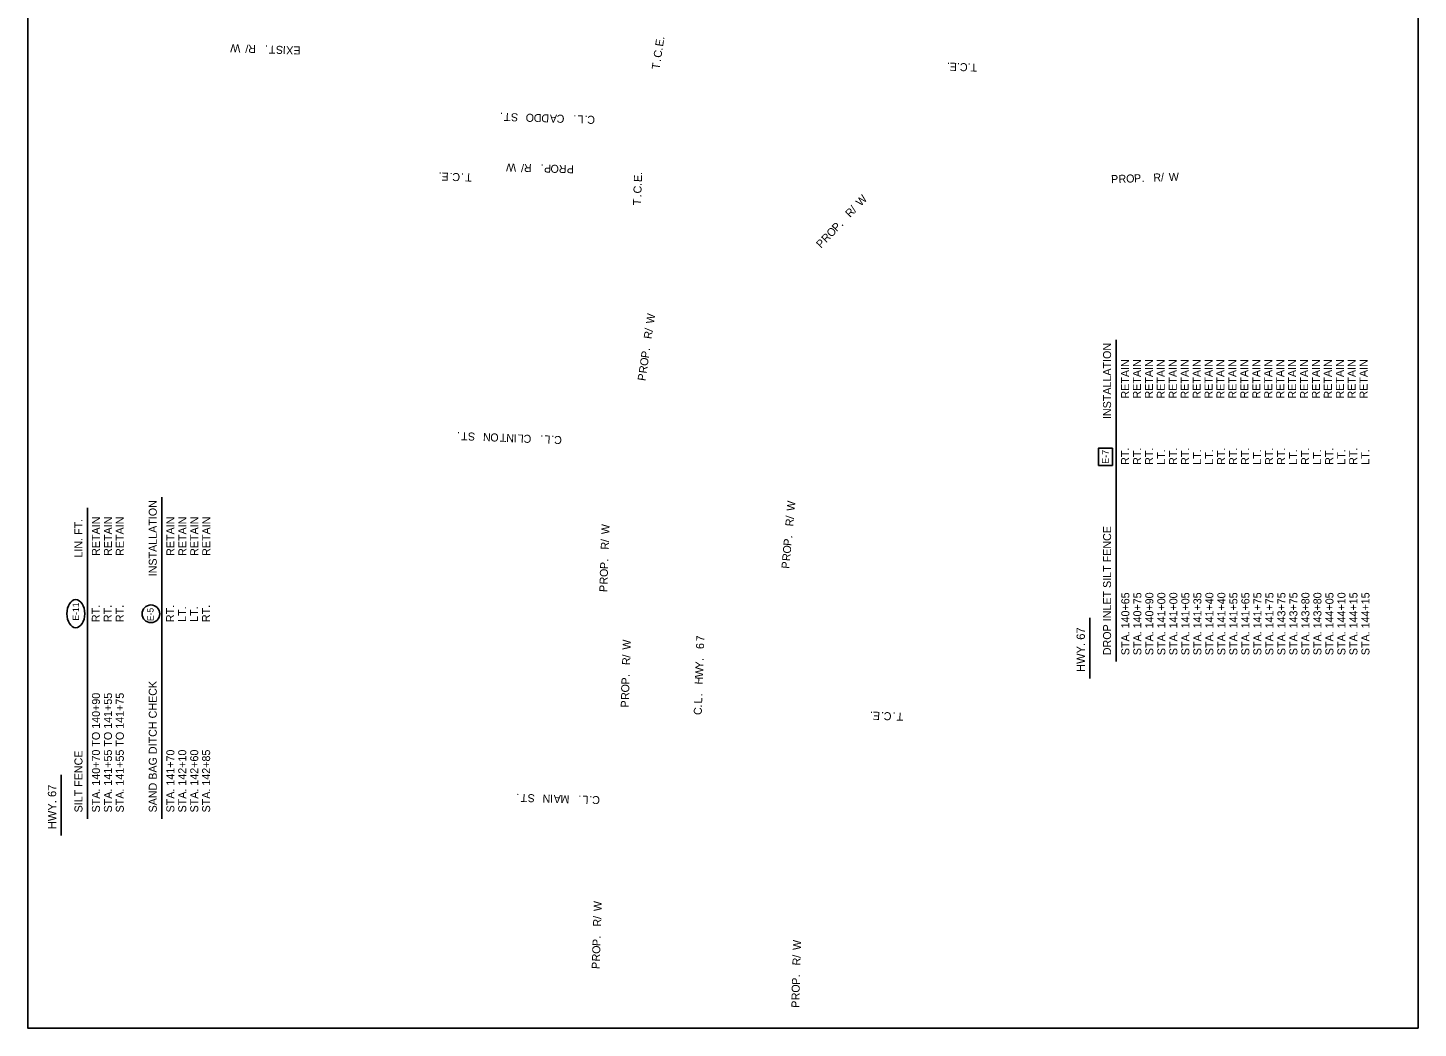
# Model space of a CAD drawing. Extents: x 991974 to 993016, y 1842702 to 1844298.
# Drawn here: x 991974 to 993016, y 1842702 to 1843452 of the extents above; entities that cross this region are included whole.
import ezdxf

# ---------------------------------------------------------------- set-up
doc = ezdxf.new("R2010")
doc.units = 0
for name, color, linetype in [('1', 7, 'Continuous'), ('44', 7, 'Continuous'), ('Default', 7, 'Continuous'), ('R_Draft', 7, 'Continuous')]:
    doc.layers.add(name, color=color, linetype=linetype)

msp = doc.modelspace()

# ---------------------------------------------------------------- linework, layer by layer
at = {"layer": '1'}
msp.add_lwpolyline([(992776.6, 1843124.1), (992776.6, 1843136.9), (992787.1, 1843136.9), (992787.1, 1843124.1)], close=True, dxfattribs=at)
msp.add_circle((992066.3, 1843012.9), 6.61, dxfattribs=at)
msp.add_ellipse((992010, 1843013), major_axis=(0, 10.5), ratio=0.638788, dxfattribs=at)
at = {"layer": '44'}
for p, q in [((992789.9, 1842977.1), (992789.9, 1843218.1)), ((992074.5, 1842859.4), (992074.5, 1843100.4)), ((992018.7, 1842859.4), (992018.7, 1843092.2)), ((992770.3, 1842964.4), (992770.3, 1843010)), ((991999.1, 1842846.7), (991999.1, 1842892.2))]:
    msp.add_line(p, q, dxfattribs=at)
at = {"layer": 'Default'}
msp.add_lwpolyline([(993016.3, 1842702.5), (991974, 1842702.5), (991974, 1843999.5), (992023.6, 1843999.5), (992023.6, 1844170.3), (992171.1, 1844170.3), (992171.1, 1844297.8), (993016.3, 1844297.8)], close=True, dxfattribs=at)
msp.add_lwpolyline([(993016.3, 1842702.5), (991974, 1842702.5), (991974, 1843999.5), (992023.6, 1843999.5), (992023.6, 1844170.3), (992171.1, 1844170.3), (992171.1, 1844297.8), (993016.3, 1844297.8)], close=True, dxfattribs=at)
msp.add_lwpolyline([(993016.3, 1842702.5), (991974, 1842702.5), (991974, 1843999.5), (992023.6, 1843999.5), (992023.6, 1844170.3), (992171.1, 1844170.3), (992171.1, 1844297.8), (993016.3, 1844297.8)], close=True, dxfattribs=at)

# ---------------------------------------------------------------- texts
at = {"layer": '1'}
for s, height, rotation, p in [('E-7 ', 5, 89.6132, (992784.3, 1843125.3)), ('E-11', 4.8, 90, (992012.4, 1843007.8)), ('E-5 ', 4.8, 90, (992068.3, 1843007.4))]:
    msp.add_text(s, height=height, rotation=rotation, dxfattribs=at).set_placement(p)
at = {"layer": '44'}
for s, height, p in [('INSTALLATION', 6, (992786.1, 1843158.8)), ('RT.', 6, (992799.6, 1843124.5)), ('RT.', 6, (992808.6, 1843124.5)), ('RT.', 6, (992817.6, 1843124.5)), ('LT.', 6, (992898.6, 1843124.6)), ('LT.', 6, (992925.6, 1843124.6)), ('LT.', 6, (992943.6, 1843124.6)), ('RT.', 6, (992952.6, 1843124.5)), ('LT.', 6, (992961.6, 1843124.6)), ('RT.', 6, (992970.6, 1843124.5)), ('LT.', 6, (992979.6, 1843124.6)), ('INSTALLATION', 6, (992070.7, 1843041)), ('LIN. FT.', 6, (992015, 1843055)), ('RETAIN', 6, (992028.1, 1843056.3)), ('RETAIN', 6, (992037.1, 1843056.3)), ('RETAIN', 6, (992046, 1843056.3)), ('DROP INLET SILT FENCE', 6, (992786.1, 1842981.9)), ('RT.', 6, (992028, 1843006.7)), ('RT.', 6, (992036.9, 1843006.7)), ('RT.', 6, (992045.9, 1843006.7)), ('HWY. 67', 6.25, (992766.5, 1842969.3)), ('SAND BAG DITCH CHECK', 6, (992070.7, 1842864.1)), ('STA. 140+70 TO 140+90', 6, (992028.1, 1842864.1)), ('STA. 141+55 TO 141+55', 6, (992037.1, 1842864.1)), ('STA. 141+55 TO 141+75', 6, (992046, 1842864.1)), ('SILT FENCE      ', 6, (992015, 1842864.1)), ('HWY. 67', 6.25, (991995.3, 1842851.5))]:
    msp.add_text(s, height=height, rotation=90, dxfattribs=at).set_placement(p)
at = {"layer": 'R_Draft'}
for s, rotation, p in [('W', 178.0557, (992133.5, 1843439.4)), ('/', 178.0557, (992139.4, 1843439.2)), ('R', 178.0557, (992145.1, 1843439)), ('.', 178.0557, (992154, 1843438.7)), ('T', 178.0557, (992159.8, 1843438.5)), ('S', 178.0557, (992165.5, 1843438.3)), ('I', 178.0557, (992167.5, 1843438.2)), ('X', 178.0557, (992173.2, 1843438)), ('E', 178.0557, (992178.6, 1843437.9)), ('E', 81.3131, (992450.2, 1843437.6)), ('.', 81.3131, (992451, 1843442.9)), ('C', 81.3131, (992448.9, 1843429.1)), ('.', 81.3131, (992448.5, 1843426.2)), ('.', 81.3131, (992449.8, 1843434.7)), ('T', 81.3131, (992447.6, 1843420.4)), ('T.C.E.', 178.0361, (992685.8, 1843425.1)), ('.', 178.1194, (992330.2, 1843388.2)), ('T', 178.1194, (992336, 1843388)), ('S', 178.1194, (992341.7, 1843387.8)), ('O', 178.1194, (992353.6, 1843387.4)), ('D', 178.1194, (992359.2, 1843387.2)), ('D', 178.1194, (992364.9, 1843387)), ('A', 178.1194, (992370.8, 1843386.8)), ('C', 178.1194, (992376.4, 1843386.7)), ('.', 178.1194, (992385.3, 1843386.4)), ('L', 178.1194, (992390.7, 1843386.2)), ('.', 178.1194, (992393.7, 1843386.1)), ('C', 178.1194, (992399.3, 1843385.9)), ('.', 178.0318, (992284.2, 1843343.5)), ('E', 178.0318, (992289.6, 1843343.3)), ('.', 178.0318, (992292.5, 1843343.2)), ('C', 178.0318, (992298.2, 1843343)), ('.', 178.0318, (992301.1, 1843342.9)), ('W', 178.425, (992340.2, 1843350.1)), ('/', 178.425, (992346.1, 1843349.9)), ('R', 178.425, (992351.8, 1843349.8)), ('.', 178.425, (992360.7, 1843349.5)), ('P', 178.425, (992366.4, 1843349.4)), ('O', 178.425, (992372.2, 1843349.2)), ('R', 178.425, (992377.9, 1843349.1)), ('P', 178.425, (992383.5, 1843348.9)), ('.', 88.0361, (992434.5, 1843341.7)), ('/', 2.1217, (992823.6, 1843336.9)), ('W', 2.1217, (992829.5, 1843337.1)), ('T', 178.0318, (992307, 1843342.7)), ('C', 88.0361, (992434, 1843327.7)), ('E', 88.0361, (992434.3, 1843336.3)), ('.', 88.0361, (992434.2, 1843333.4)), ('P', 2.1217, (992786.2, 1843335.5)), ('R', 2.1217, (992791.8, 1843335.7)), ('O', 2.1217, (992797.5, 1843335.9)), ('P', 2.1217, (992803.4, 1843336.1)), ('.', 2.1217, (992809, 1843336.4)), ('R', 2.1217, (992817.9, 1843336.7)), ('T', 88.0361, (992433.7, 1843318.9)), ('.', 88.0361, (992433.9, 1843324.8)), ('W', 46.5037, (992598.5, 1843317.8)), ('R', 46.5037, (992590.5, 1843309.4)), ('/', 46.5037, (992594.4, 1843313.5)), ('O', 46.5037, (992576.5, 1843294.6)), ('P', 46.5037, (992580.5, 1843298.8)), ('.', 46.5037, (992584.4, 1843302.9)), ('P', 46.5037, (992568.7, 1843286.4)), ('R', 46.5037, (992572.6, 1843290.5)), ('W', 81.6959, (992443.3, 1843229.9)), ('R', 81.6959, (992441.6, 1843218.5)), ('/', 81.6959, (992442.5, 1843224.1)), ('P', 81.6959, (992439.5, 1843204.1)), ('.', 81.6959, (992440.3, 1843209.7)), ('R', 81.6959, (992437.9, 1843192.7)), ('O', 81.6959, (992438.7, 1843198.3)), ('RETAIN', 90, (992799.6, 1843174.2)), ('RETAIN', 90, (992808.5, 1843174.2)), ('RETAIN', 90, (992817.5, 1843174.2)), ('RETAIN', 90, (992826.4, 1843174.2)), ('RETAIN', 90, (992835.4, 1843174.2)), ('RETAIN', 90, (992844.3, 1843174.2)), ('RETAIN', 90, (992853.3, 1843174.2)), ('RETAIN', 90, (992862.2, 1843174.2)), ('RETAIN', 90, (992871.1, 1843174.2)), ('RETAIN', 90, (992880.1, 1843174.2)), ('RETAIN', 90, (992889, 1843174.2)), ('RETAIN', 90, (992898, 1843174.2)), ('RETAIN', 90, (992906.9, 1843174.2)), ('RETAIN', 90, (992915.9, 1843174.2)), ('RETAIN', 90, (992924.8, 1843174.2)), ('RETAIN', 90, (992933.8, 1843174.2)), ('RETAIN', 90, (992942.7, 1843174.2)), ('RETAIN', 90, (992951.6, 1843174.2)), ('RETAIN', 90, (992960.6, 1843174.2)), ('RETAIN', 90, (992969.5, 1843174.2)), ('RETAIN', 90, (992978.4, 1843174.2)), ('P', 81.6959, (992437, 1843187.1)), ('.', 177.7861, (992298, 1843149)), ('T', 177.7861, (992303.9, 1843148.8)), ('S', 177.7861, (992309.5, 1843148.6)), ('N', 177.7861, (992321.2, 1843148.1)), ('O', 177.7861, (992327.1, 1843147.9)), ('T', 177.7861, (992332.9, 1843147.7)), ('N', 177.7861, (992338.6, 1843147.4)), ('I', 177.7861, (992340.6, 1843147.4)), ('L', 177.7861, (992345.9, 1843147.1)), ('C', 177.7861, (992351.6, 1843146.9)), ('.', 177.7861, (992360.5, 1843146.6)), ('L', 177.7861, (992365.9, 1843146.4)), ('.', 177.7861, (992368.8, 1843146.3)), ('C', 177.7861, (992374.5, 1843146)), ('LT.', 90, (992826.6, 1843124.6)), ('RT.', 90, (992835.6, 1843124.5)), ('RT.', 90, (992844.6, 1843124.5)), ('LT.', 90, (992853.6, 1843124.6)), ('LT.', 90, (992862.6, 1843124.6)), ('RT.', 90, (992871.6, 1843124.5)), ('RT.', 90, (992880.6, 1843124.5)), ('RT.', 90, (992889.6, 1843124.5)), ('RT.', 90, (992907.6, 1843124.5)), ('RT.', 90, (992916.6, 1843124.5)), ('RT.', 90, (992934.6, 1843124.5)), ('W', 84.7809, (992548.8, 1843089.7)), ('RETAIN', 90, (992083.9, 1843056.3)), ('RETAIN', 90, (992092.9, 1843056.3)), ('RETAIN', 90, (992101.8, 1843056.3)), ('RETAIN', 90, (992110.8, 1843056.3)), ('R', 84.7809, (992547.8, 1843078.2)), ('/', 84.7809, (992548.3, 1843083.8)), ('W', 88.0361, (992409.9, 1843072.4)), ('/', 88.0361, (992409.7, 1843066.5)), ('R', 88.0361, (992409.5, 1843060.9)), ('O', 84.7809, (992545.9, 1843057.8)), ('P', 84.7809, (992546.4, 1843063.6)), ('.', 84.7809, (992547, 1843069.3)), ('P', 88.0361, (992409, 1843046.3)), ('.', 88.0361, (992409.2, 1843052)), ('P', 84.7809, (992544.9, 1843046.5)), ('R', 84.7809, (992545.4, 1843052.2)), ('O', 88.0361, (992408.8, 1843040.4)), ('P', 88.0361, (992408.4, 1843029.1)), ('R', 88.0361, (992408.6, 1843034.8)), ('STA. 140+65', 90, (992799.8, 1842981.9)), ('STA. 140+75', 90, (992808.8, 1842981.9)), ('STA. 140+90', 90, (992817.8, 1842981.9)), ('STA. 141+00', 90, (992826.8, 1842981.9)), ('STA. 141+00', 90, (992835.8, 1842981.9)), ('STA. 141+05', 90, (992844.8, 1842981.9)), ('STA. 141+35', 90, (992853.8, 1842981.9)), ('STA. 141+40', 90, (992862.8, 1842981.9)), ('STA. 141+40', 90, (992871.8, 1842981.9)), ('STA. 141+55', 90, (992880.8, 1842981.9)), ('STA. 141+65', 90, (992889.8, 1842981.9)), ('STA. 141+75', 90, (992898.8, 1842981.9)), ('STA. 141+75', 90, (992907.8, 1842981.9)), ('STA. 143+75', 90, (992916.8, 1842981.9)), ('STA. 143+75', 90, (992925.8, 1842981.9)), ('STA. 143+80', 90, (992934.8, 1842981.9)), ('STA. 143+80', 90, (992943.8, 1842981.9)), ('STA. 144+05', 90, (992952.8, 1842981.9)), ('STA. 144+10', 90, (992961.8, 1842981.9)), ('STA. 144+15', 90, (992970.8, 1842981.9)), ('STA. 144+15', 90, (992979.8, 1842981.9)), ('RT.', 90, (992083.7, 1843006.7)), ('LT.', 90, (992092.7, 1843006.9)), ('LT.', 90, (992101.6, 1843006.9)), ('RT.', 90, (992110.6, 1843006.7)), ('W', 88.2135, (992425.8, 1842985.9)), ('6', 88.0361, (992480.9, 1842986.4)), ('7', 88.0361, (992481.1, 1842992.1)), ('/', 88.2135, (992425.7, 1842980)), ('R', 88.2135, (992425.5, 1842974.4)), ('.', 88.0361, (992480.6, 1842977.5)), ('W', 88.0361, (992480.2, 1842965.3)), ('Y', 88.0361, (992480.4, 1842971.8)), ('O', 88.2135, (992424.8, 1842953.9)), ('P', 88.2135, (992425, 1842959.8)), ('.', 88.2135, (992425.2, 1842965.5)), ('H', 88.0361, (992480, 1842959.9)), ('P', 88.2135, (992424.5, 1842942.6)), ('R', 88.2135, (992424.7, 1842948.3)), ('L', 88.0361, (992479.5, 1842945.6)), ('.', 88.0361, (992479.7, 1842951)), ('C', 88.0361, (992479.2, 1842937)), ('.', 88.0361, (992479.4, 1842942.7)), ('.', 178.0361, (992607.7, 1842939.6)), ('E', 178.0361, (992613, 1842939.4)), ('.', 178.0361, (992616, 1842939.3)), ('C', 178.0361, (992621.6, 1842939.1)), ('.', 178.0361, (992624.6, 1842939)), ('T', 178.0361, (992630.4, 1842938.8)), ('STA. 141+70', 90, (992083.9, 1842864.1)), ('STA. 142+10', 90, (992092.8, 1842864.1)), ('STA. 142+60', 90, (992101.8, 1842864.1)), ('STA. 142+85', 90, (992110.7, 1842864.1)), ('.', 178.3694, (992342.6, 1842878)), ('T', 178.3694, (992348.5, 1842877.8)), ('S', 178.3694, (992354.2, 1842877.7)), ('N', 178.3694, (992365.8, 1842877.3)), ('I', 178.3694, (992367.8, 1842877.3)), ('A', 178.3694, (992373.7, 1842877.1)), ('M', 178.3694, (992380.1, 1842876.9)), ('.', 178.3694, (992389, 1842876.7)), ('L', 178.3694, (992394.4, 1842876.5)), ('.', 178.3694, (992397.3, 1842876.4)), ('C', 178.3694, (992403, 1842876.3)), ('W', 88.2135, (992404.1, 1842790)), ('/', 88.2135, (992403.9, 1842784.2)), ('R', 88.2135, (992403.7, 1842778.5)), ('.', 88.2135, (992403.4, 1842769.6)), ('O', 88.2135, (992403.1, 1842758.1)), ('P', 88.2135, (992403.3, 1842763.9)), ('W', 88.2437, (992553.5, 1842760.9)), ('P', 88.2135, (992402.7, 1842746.7)), ('R', 88.2135, (992402.9, 1842752.4)), ('/', 88.3031, (992553.3, 1842755.1)), ('R', 88.3605, (992553.2, 1842749.4)), ('P', 88.5084, (992552.8, 1842734.9)), ('.', 88.4509, (992552.9, 1842740.5)), ('R', 88.6251, (992552.5, 1842723.3)), ('O', 88.5677, (992552.6, 1842729)), ('P', 88.6826, (992552.4, 1842717.7))]:
    msp.add_text(s, height=6, rotation=rotation, dxfattribs=at).set_placement(p)

doc.saveas('drawing.dxf')
